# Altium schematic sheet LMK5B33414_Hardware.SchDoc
size B; Date: Not shown in title block; ApprovedBy: Not shown in title block; CheckedBy: Not shown in title block; Author: Not shown in title block; CompanyName: Not shown in title block; Engineer: Not shown in title block; Organization: Not shown in title block; Address1: Not shown in title block; Address2: Not shown in title block; Address3: Not shown in title block; Address4: Not shown in title block; DocumentNumber: 3; Revision: Use project parameter SCH_Rev; SheetNumber: 3; SheetTotal: 3; PageSetup: Record=PageOptions¦CenterHorizontal=True¦CenterVertical=True¦PrintScale=1.00¦XCorrection=1.00¦YCorrection=1.00¦PrintKind=0¦BorderSize=5000000¦LeftOffset=0¦BottomOffset=0¦Orientation=2¦PaperLength=1000¦PaperWidth=1000¦Scale=100¦PaperSource=15¦PrintQuality=600¦MediaType=1¦DitherType=10¦PaperKind=Letter¦PrintScaleMode=1
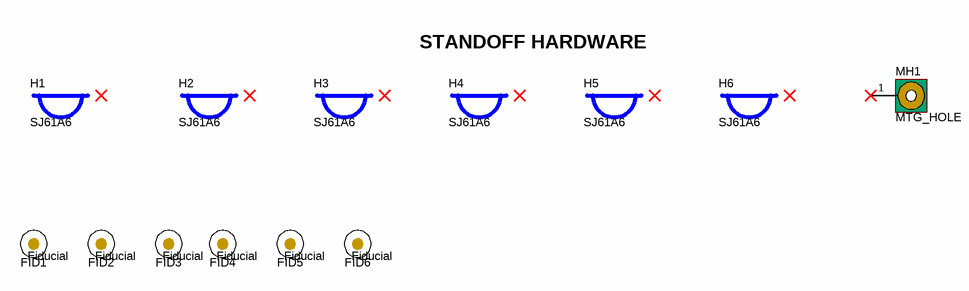
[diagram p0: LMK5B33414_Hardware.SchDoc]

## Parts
FID1  Fiducial  [Fiducial10-20]
FID2  Fiducial  [Fiducial10-20]
FID3  Fiducial  [Fiducial10-20]
FID4  Fiducial  [Fiducial10-20]
FID5  Fiducial  [Fiducial10-20]
FID6  Fiducial  [Fiducial10-20]
H1  SJ61A6  [3M_SJ61A6]
H2  SJ61A6  [3M_SJ61A6]
H3  SJ61A6  [3M_SJ61A6]
H4  SJ61A6  [3M_SJ61A6]
H5  SJ61A6  [3M_SJ61A6]
H6  SJ61A6  [3M_SJ61A6]
MH1  MTG_HOLE  [MTGP_252mil_157mil_6Via]  (no BOM)

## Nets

Not connected (* = marked no-connect by the designer): MH1 1*

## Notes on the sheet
- STANDOFF HARDWARE

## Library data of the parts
FID1-FID6 = CMP-0077181-1: Fiducial mark.  There is nothing to buy or mount.
H1-H6 = CMP-0079645-1: BUMPER CYLIN 0.312" DIA; Manufacturer: 3M; Green_Lifecycle: Not Set; Green_REACh: Incomplete
MH1 = CMP-0078422-2: PCB Mounting Hole; Manufacturer: Any; Key: Mounting Hole (non-standard)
